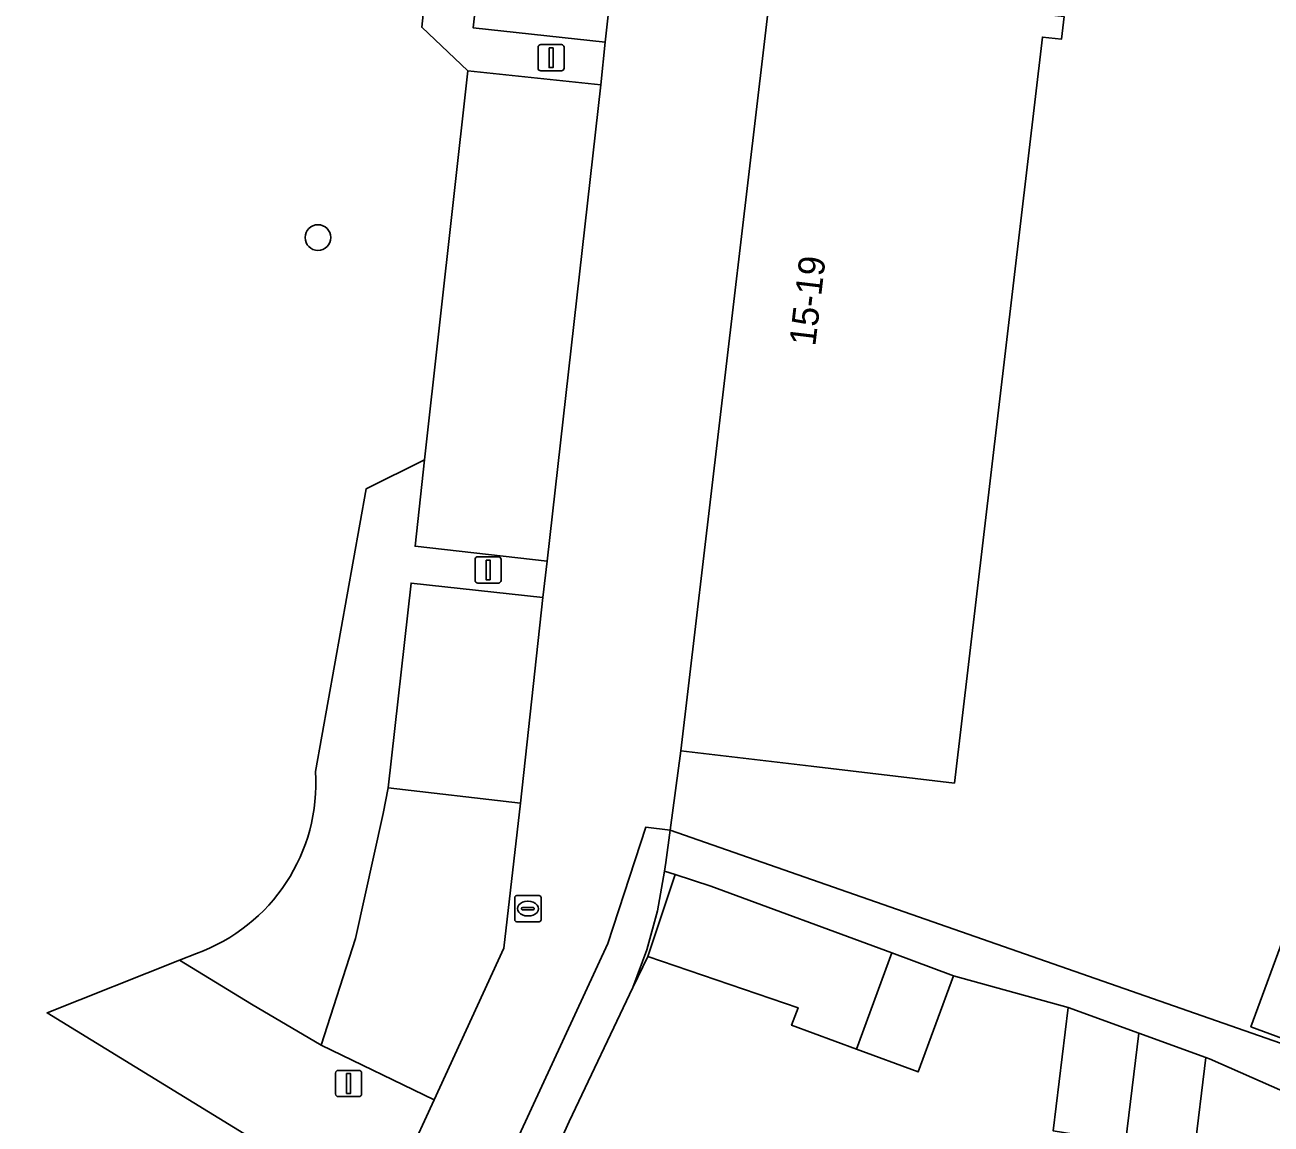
# Model space of a CAD drawing. Extents: x 161692 to 162379, y 380760 to 381678.
# Drawn here: x 161872.36 to 161919.85, y 381057.99 to 381099.87 of the extents above; entities that cross this region are included whole.
import ezdxf

# ---------------------------------------------------------------- set-up
doc = ezdxf.new("R2010")
doc.units = 0
for name, color, linetype in [('IMGEO_Boom', 7, 'Continuous'), ('IMGEO_Erf', 7, 'Continuous'), ('IMGEO_Groenvoorziening', 7, 'Continuous'), ('IMGEO_Lichtmast', 7, 'Continuous'), ('IMGEO_Muur', 7, 'Continuous'), ('IMGEO_Pand', 7, 'Continuous'), ('IMGEO_Pand_nummerreeks', 7, 'Continuous'), ('IMGEO_Parkeervlak_open', 7, 'Continuous'), ('IMGEO_Rijbaan_lokaal_open', 7, 'Continuous'), ('IMGEO_Rioolput', 7, 'Continuous'), ('IMGEO_Voetpad_open', 7, 'Continuous')]:
    doc.layers.add(name, color=color, linetype=linetype)

msp = doc.modelspace()

# ---------------------------------------------------------------- linework, layer by layer
at = {"layer": 'IMGEO_Boom'}
msp.add_circle((161883.524, 381091.768), 0.489, dxfattribs=at)
at = {"layer": 'IMGEO_Erf'}
for points in [[(161911.96, 381100.185), (161911.858, 381099.322), (161911.136, 381099.407), (161907.782, 381070.978), (161902.322, 381071.622), (161897.356, 381072.208), (161896.944, 381069.188), (161924.793, 381059.467)], [(161911.543, 381057.735), (161912.118, 381062.433), (161907.751, 381063.641), (161906.399, 381059.976), (161904.046, 381060.844), (161901.576, 381061.755), (161901.823, 381062.423), (161896.095, 381064.377), (161897.136, 381067.502), (161896.735, 381067.622), (161896.466, 381066.111), (161896.063, 381064.63), (161895.529, 381063.191), (161893.094, 381058.084), (161889.005, 381049.024)], [(161924.831, 381059.577), (161919.079, 381061.699), (161920.461, 381065.447)], [(161922.667, 381058.201), (161917.5, 381060.471), (161917.362, 381060.521), (161916.914, 381056.87)]]:
    msp.add_lwpolyline(points, dxfattribs=at)
at = {"layer": 'IMGEO_Groenvoorziening'}
for points in [[(161889.237, 381098.122), (161887.481, 381099.78), (161889.509, 381119.184), (161891.249, 381120.655), (161892.607, 381122.097), (161890.302, 381128.132), (161871.724, 381120.949), (161866.545, 381106.35), (161863.772, 381105.601), (161863.248, 381101.216), (161862.407, 381093.385), (161863.41, 381093.267), (161863.195, 381091.592), (161862.202, 381091.684), (161860.9, 381080.876), (161860.594, 381078.32), (161862.509, 381077.782), (161863.62, 381075.409), (161863.759, 381073.519), (161864.131, 381072.768), (161864.237, 381067.43), (161859.466, 381070.205)], [(161883.43, 381071.42), (161885.362, 381082.198), (161887.589, 381083.293), (161889.237, 381098.122)], [(161886.01, 381069.819), (161886.203, 381070.796), (161887.075, 381078.601), (161892.097, 381078.052), (161892.263, 381079.432), (161887.224, 381080.003), (161887.589, 381083.293), (161885.362, 381082.198), (161883.43, 381071.42)], [(161878.889, 381064.485), (161878.244, 381064.228), (161880.995, 381062.556), (161883.649, 381060.994), (161884.958, 381065.063), (161886.01, 381069.819)], [(161857.693, 381064.752), (161858.502, 381064.372), (161883.582, 381049.424), (161885.89, 381054.437), (161873.202, 381062.221), (161878.244, 381064.228), (161878.889, 381064.485)]]:
    msp.add_lwpolyline(points, dxfattribs=at)
for points in [[(161890.857, 381112.602), (161891.249, 381120.655), (161889.509, 381119.184), (161887.481, 381099.78), (161889.237, 381098.122), (161894.31, 381097.589), (161894.473, 381099.213), (161889.443, 381099.757)], [(161891.241, 381070.22), (161886.203, 381070.796), (161886.01, 381069.819), (161884.958, 381065.063), (161883.649, 381060.994), (161887.953, 381058.917), (161890.614, 381064.695)], [(161883.649, 381060.994), (161880.995, 381062.556), (161878.244, 381064.228), (161873.202, 381062.221), (161885.89, 381054.437), (161887.953, 381058.917)]]:
    msp.add_lwpolyline(points, close=True, dxfattribs=at)
msp.add_arc((161876.54, 381070.977), 6.904, 289.8903, 3.6766, dxfattribs=at)
msp.add_arc((161876.54, 381070.977), 6.904, 289.8903, 3.6766, dxfattribs=at)
at = {"layer": 'IMGEO_Lichtmast'}
for p, q in [((161892.015, 381099.12), (161892.805, 381099.12)), ((161892.805, 381099.12), (161892.015, 381099.12)), ((161891.915, 381098.22), (161891.915, 381099.02)), ((161891.915, 381099.02), (161891.915, 381098.22)), ((161892.905, 381099.02), (161892.905, 381098.22)), ((161892.905, 381098.22), (161892.905, 381099.02)), ((161892.805, 381098.12), (161892.015, 381098.12)), ((161892.015, 381098.12), (161892.805, 381098.12)), ((161889.612, 381079.605), (161890.402, 381079.605)), ((161890.402, 381079.605), (161889.612, 381079.605)), ((161889.512, 381078.705), (161889.512, 381079.505)), ((161889.512, 381079.505), (161889.512, 381078.705)), ((161890.502, 381079.505), (161890.502, 381078.705)), ((161890.502, 381078.705), (161890.502, 381079.505)), ((161890.402, 381078.605), (161889.612, 381078.605)), ((161889.612, 381078.605), (161890.402, 381078.605)), ((161884.197, 381059.134), (161884.197, 381059.934)), ((161884.197, 381059.934), (161884.197, 381059.134)), ((161884.297, 381060.034), (161885.087, 381060.034)), ((161885.087, 381060.034), (161884.297, 381060.034)), ((161885.187, 381059.934), (161885.187, 381059.134)), ((161885.187, 381059.134), (161885.187, 381059.934)), ((161885.087, 381059.034), (161884.297, 381059.034)), ((161884.297, 381059.034), (161885.087, 381059.034))]:
    msp.add_line(p, q, dxfattribs=at)
for points in [[(161892.335, 381098.995), (161892.485, 381098.995), (161892.485, 381098.245), (161892.335, 381098.245), (161892.335, 381098.995)], [(161889.932, 381079.48), (161890.082, 381079.48), (161890.082, 381078.73), (161889.932, 381078.73), (161889.932, 381079.48)], [(161884.617, 381059.909), (161884.767, 381059.909), (161884.767, 381059.159), (161884.617, 381059.159), (161884.617, 381059.909)]]:
    msp.add_lwpolyline(points, dxfattribs=at)
for centre, start, end in [((161892.015, 381099.02), 90, 180), ((161892.015, 381099.02), 90, 180), ((161892.805, 381099.02), 0, 90), ((161892.805, 381099.02), 360, 90), ((161892.015, 381098.22), 180, 270), ((161892.015, 381098.22), 180, 270), ((161892.805, 381098.22), 270, 0), ((161892.805, 381098.22), 270, 0), ((161889.612, 381079.505), 90, 180), ((161889.612, 381079.505), 90, 180), ((161890.402, 381079.505), 0, 90), ((161890.402, 381079.505), 360, 90), ((161889.612, 381078.705), 180, 270), ((161889.612, 381078.705), 180, 270), ((161890.402, 381078.705), 270, 0), ((161890.402, 381078.705), 270, 0), ((161884.297, 381059.934), 90, 180), ((161884.297, 381059.934), 90, 180), ((161885.087, 381059.934), 0, 90), ((161885.087, 381059.934), 360, 90), ((161884.297, 381059.134), 180, 270), ((161884.297, 381059.134), 180, 270), ((161885.087, 381059.134), 270, 0), ((161885.087, 381059.134), 270, 0)]:
    msp.add_arc(centre, 0.1, start, end, dxfattribs=at)
at = {"layer": 'IMGEO_Muur'}
for points in [[(161895.529, 381063.191), (161896.095, 381064.377)], [(161893.094, 381058.084), (161895.529, 381063.191)]]:
    msp.add_lwpolyline(points, dxfattribs=at)
at = {"layer": 'IMGEO_Pand'}
for points in [[(161902.322, 381071.622), (161907.782, 381070.978), (161911.136, 381099.407), (161911.858, 381099.322), (161911.96, 381100.185), (161911.256, 381100.268), (161912.109, 381107.49), (161906.614, 381108.139), (161901.665, 381108.723), (161897.356, 381072.208)], [(161905.396, 381064.51), (161898.496, 381067.056), (161897.136, 381067.502), (161896.095, 381064.377), (161901.823, 381062.423), (161901.576, 381061.755), (161904.046, 381060.844)], [(161924.831, 381059.577), (161926.214, 381063.326), (161920.461, 381065.447), (161919.079, 381061.699)], [(161905.396, 381064.51), (161904.046, 381060.844), (161906.399, 381059.976), (161907.751, 381063.641)], [(161914.809, 381061.452), (161912.118, 381062.433), (161911.543, 381057.735), (161914.299, 381057.291)], [(161917.362, 381060.521), (161914.809, 381061.452), (161914.299, 381057.291), (161916.914, 381056.87)]]:
    msp.add_lwpolyline(points, close=True, dxfattribs=at)
at = {"layer": 'IMGEO_Parkeervlak_open'}
for points in [[(161895.912, 381112.139), (161890.857, 381112.602), (161889.443, 381099.757), (161894.473, 381099.213)], [(161894.31, 381097.589), (161889.237, 381098.122), (161887.589, 381083.293), (161887.224, 381080.003), (161892.263, 381079.432)], [(161892.097, 381078.052), (161887.075, 381078.601), (161886.203, 381070.796), (161891.241, 381070.22)]]:
    msp.add_lwpolyline(points, close=True, dxfattribs=at)
at = {"layer": 'IMGEO_Rijbaan_lokaal_open'}
msp.add_lwpolyline([(161901.665, 381108.723), (161902.009, 381111.747), (161901.747, 381112.421), (161899.888, 381112.731), (161893.576, 381129.276), (161890.302, 381128.132), (161892.607, 381122.097), (161896.009, 381113.169), (161895.912, 381112.139), (161894.473, 381099.213), (161894.31, 381097.589), (161892.263, 381079.432), (161892.097, 381078.052), (161891.241, 381070.22), (161890.614, 381064.695), (161887.953, 381058.917), (161885.89, 381054.437), (161883.582, 381049.424), (161886.556, 381047.541), (161894.574, 381064.871), (161896.026, 381069.305), (161896.944, 381069.188), (161897.356, 381072.208)], close=True, dxfattribs=at)
at = {"layer": 'IMGEO_Rioolput'}
for p, q in [((161891.024, 381065.771), (161891.024, 381066.623)), ((161891.099, 381066.697), (161891.951, 381066.697)), ((161891.512, 381066.477), (161891.537, 381066.477)), ((161892.025, 381066.623), (161892.025, 381065.771)), ((161891.283, 381066.191), (161891.283, 381066.203)), ((161891.721, 381066.154), (161891.323, 381066.154)), ((161891.326, 381066.24), (161891.724, 381066.24)), ((161891.535, 381065.917), (161891.51, 381065.917)), ((161891.767, 381066.203), (161891.767, 381066.191)), ((161891.951, 381065.697), (161891.099, 381065.697))]:
    msp.add_line(p, q, dxfattribs=at)
for points in [[(161891.024, 381065.771), (161891.024, 381066.623)], [(161891.099, 381066.697), (161891.951, 381066.697)], [(161892.025, 381066.623), (161892.025, 381065.771)], [(161891.951, 381065.697), (161891.099, 381065.697)]]:
    msp.add_lwpolyline(points, dxfattribs=at)
for centre, radius, start, end in [((161891.101, 381066.621), 0.0765, 91.552, 178.448), ((161891.101, 381066.621), 0.0765, 91.552, 178.448), ((161891.949, 381066.621), 0.0765, 1.552, 88.448), ((161891.949, 381066.621), 0.0765, 1.552, 88.448), ((161891.323, 381066.2), 0.0403, 85.8775, 175.7526), ((161891.32, 381066.19), 0.0366, 178.938, 274.7102), ((161891.724, 381066.197), 0.043, 264.8664, 352.4533), ((161891.728, 381066.202), 0.0386, 1.7309, 96.639), ((161891.101, 381065.773), 0.0765, 181.552, 268.448), ((161891.101, 381065.773), 0.0765, 181.552, 268.448), ((161891.949, 381065.773), 0.0765, 271.552, 358.448), ((161891.949, 381065.773), 0.0765, 271.552, 358.448)]:
    msp.add_arc(centre, radius, start, end, dxfattribs=at)
for centre, major_axis, ratio, start_param, end_param in [((161891.511, 381066.197), (-0.387, 0.002), 0.722429, 4.712389, 7.853982), ((161891.536, 381066.197), (-0.39, 0.002), 0.717154, 1.570796, 4.712389)]:
    msp.add_ellipse(centre, major_axis=major_axis, ratio=ratio, start_param=start_param, end_param=end_param, dxfattribs=at)
at = {"layer": 'IMGEO_Voetpad_open'}
for points in [[(161889.005, 381049.024), (161893.094, 381058.084), (161895.529, 381063.191), (161896.063, 381064.63), (161896.466, 381066.111), (161896.735, 381067.622), (161896.776, 381067.959), (161896.944, 381069.188), (161896.026, 381069.305), (161894.574, 381064.871), (161886.556, 381047.541)], [(161924.793, 381059.467), (161896.944, 381069.188), (161896.776, 381067.959), (161896.735, 381067.622), (161897.136, 381067.502), (161898.496, 381067.056), (161905.396, 381064.51), (161907.751, 381063.641), (161912.118, 381062.433), (161914.809, 381061.452), (161917.362, 381060.521), (161917.5, 381060.471), (161922.667, 381058.201)]]:
    msp.add_lwpolyline(points, dxfattribs=at)

# ---------------------------------------------------------------- texts
at = {"layer": 'IMGEO_Pand_nummerreeks'}
msp.add_text('15-19', height=1, rotation=83.2699, dxfattribs=at).set_placement((161902.476, 381087.605))

doc.saveas('drawing.dxf')
